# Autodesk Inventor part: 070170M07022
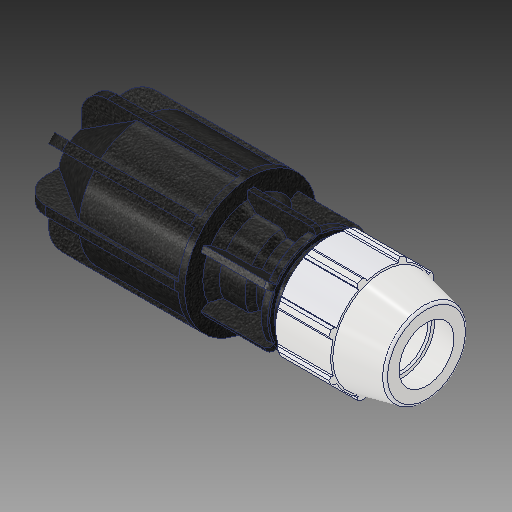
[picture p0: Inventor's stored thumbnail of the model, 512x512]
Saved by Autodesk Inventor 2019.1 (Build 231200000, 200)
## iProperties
Created: 2017-02
Part Number: 070170M07022
Material: PVC-Piping
Description: PLASSON PLASS4 COUPLING 3/4'' - 0.73
Document SubType Name: Modeling
Designer: KIM
Mass: 92.6774 g
Surface Area: 199.44 cm^2
Volume: 66.1981 cm^3
Density: 1.4 g/cm^3
Appearance: PTFE
Author: KIM
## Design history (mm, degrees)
derived "070170M0.ipt"
feature "Solid1::070170M0.ipt"
tag "TaggingFeature1"
body "Solid1"
other parameters: "d_" = 26.6, "E_" = 54.102, "A_" = 81, "l_" = 59.944, "d_1" = 18.542, "E_1" = 64.008, "l_1" = 80.01, "H_" = 165.1, "d106" = 32.9921, "d2" = 26.6, "d4" = 11.79286, "d5" = 20.9804, "d7" = 54.102, "d8" = 32.9921, "d9" = 11.57143, "d11" = 4.1275, "d12" = 43.2816, "d13" = 120 deg, "d14" = 39.9, "d15" = 12 deg, "d16" = 48.6918, "d18" = 1.33, "d19" = 35 deg, "d20" = 17.5 deg, "d21" = 50.31486, "d23" = 0, "d25" = 360 deg, "d27" = 1.08204, "d42" = 26.9748, "d43" = 1.62306, "d46" = 0.798, "d53" = 0.532, "d67" = 2.7051, "d70" = 23.94, "d71" = 59.944, "d74" = 180 deg, "d75" = 18.542, "d76" = 64.008, "d80" = 23.94, "d84" = 60.8076, "d85" = 135 deg, "d86" = 3.2004, "d89" = 3.2004, "d90" = 135 deg, "d94" = 3.2004, "d97" = 4.32816, "d98" = 0, "d100" = 360 deg, "d102" = 70.4088, "d103" = 12.8016, "d104" = 5.12064, "d105" = 0, "d110" = 80.01, "d112" = 99.06, "d113" = 27.2034, "d114" = 66.04, "d115" = 38.4048, "d116" = 99.06, "d117" = 4.0005, "d118" = 27.051, "d119" = 2.7051, "d120" = 0, "d121" = 2.7051, "d123" = 360 deg
